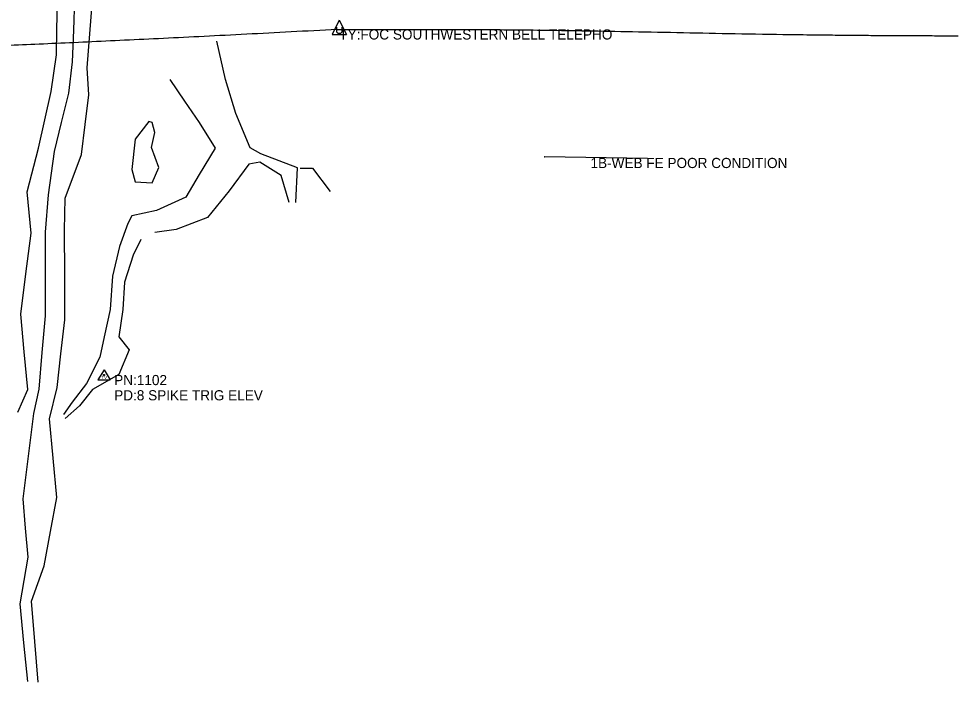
# Model space of a CAD drawing. Extents: x 976456 to 985170, y 1525951 to 1527080.
# Drawn here: x 982881.4 to 983344, y 1525950.6 to 1526277.2 of the extents above; entities that cross this region are included whole.
import ezdxf

# ---------------------------------------------------------------- set-up
doc = ezdxf.new("R2010")
doc.units = 0
for name, color, linetype in [('S_DITCHLINE', 7, 'Continuous'), ('S_FENCE', 7, 'Continuous'), ('S_FIBER_OPTIC_CABLE', 7, 'Continuous'), ('S_MSC_PT_SYM', 7, 'Continuous'), ('S_SECONDARY_CTL', 7, 'Continuous'), ('S_SECONDARY_CTL_ANNOT', 7, 'Continuous'), ('S_STREAM', 7, 'Continuous'), ('S_SURVEY_TEXT_ANNOT', 7, 'Continuous'), ('S_UNDERGROUND_CABLE', 7, 'Continuous'), ('S_UTILITY_POLE_ANNOT', 7, 'Continuous')]:
    doc.layers.add(name, color=color, linetype=linetype)

msp = doc.modelspace()

# ---------------------------------------------------------------- linework, layer by layer
at = {"layer": 'S_DITCHLINE'}
for points in [[(983017.87, 1526186.79), (983018.61, 1526203.88), (983000.6, 1526210.79), (982995.33, 1526213.63), (982988.23, 1526230.62), (982983.19, 1526247.38), (982978.84, 1526266.28)], [(982955.72, 1526247.28), (982962.94, 1526236.71), (982970.15, 1526226.13), (982978.07, 1526213.6), (982970.21, 1526200.62), (982963.63, 1526189.41), (982949.16, 1526182.77), (982937.08, 1526180.12), (982935.06, 1526176.37), (982930.93, 1526165.11), (982927.61, 1526150.46), (982926.38, 1526134.1), (982923.45, 1526120.61), (982921.28, 1526110.67), (982914.7, 1526097.64), (982907.73, 1526088.52), (982903.37, 1526082.32)], [(983014.54, 1526186.73), (983010.67, 1526200.06), (983000.04, 1526206.58), (982994.65, 1526205.64), (982985.01, 1526192.59), (982974.38, 1526179.43), (982958.93, 1526173.53), (982948.4, 1526172.01)], [(983019.88, 1526203.75), (983026.02, 1526203.6), (983034.8, 1526192.25)], [(982941.46, 1526168.58), (982937.64, 1526160.83), (982933.41, 1526147.54), (982932.67, 1526134.05), (982930.64, 1526120.7), (982935.79, 1526114.19), (982930.71, 1526102.09), (982917.74, 1526094.62), (982911.35, 1526086.71), (982904.16, 1526080.48)]]:
    msp.add_lwpolyline(points, dxfattribs=at)
msp.add_lwpolyline([(982945.37, 1526226.68), (982938.78, 1526217.88), (982937.05, 1526202.94), (982938.72, 1526196.93), (982947.05, 1526196.46), (982950.29, 1526204.02), (982946.78, 1526213.93), (982948.39, 1526221.18), (982947.09, 1526226.08)], close=True, dxfattribs=at)
at = {"layer": 'S_FENCE'}
msp.add_line((983191.06, 1526208.5), (983140.2, 1526209.24), dxfattribs=at)
at = {"layer": 'S_FIBER_OPTIC_CABLE'}
for points in [[(983038.02, 1526271.95), (982776.59, 1526257.91), (982699.02, 1526265.54), (982301.76, 1526204.82)], [(983038.02, 1526271.95), (983068.37, 1526271.95), (983136.25, 1526271.95), (983282.54, 1526268.9), (983343.98, 1526268.9)]]:
    msp.add_open_spline(points, degree=2, dxfattribs=at)
at = {"layer": 'S_MSC_PT_SYM'}
for points in [[(983140.2, 1526209.24), (983140.2, 1526209.29), (983140.2, 1526209.24), (983140.15, 1526209.24), (983140.2, 1526209.24), (983140.2, 1526209.19), (983140.2, 1526209.24), (983140.25, 1526209.24)], [(983162.92, 1526208.73), (983162.92, 1526208.78), (983162.92, 1526208.73), (983162.87, 1526208.73), (983162.92, 1526208.73), (983162.92, 1526208.68), (983162.92, 1526208.73), (983162.97, 1526208.73)], [(983191.06, 1526208.5), (983191.06, 1526208.55), (983191.06, 1526208.5), (983191.01, 1526208.5), (983191.06, 1526208.5), (983191.06, 1526208.45), (983191.06, 1526208.5), (983191.11, 1526208.5)]]:
    msp.add_lwpolyline(points, dxfattribs=at)
at = {"layer": 'S_SECONDARY_CTL'}
for p, q in [((982923.37, 1526104.45), (982920.36, 1526099.49)), ((982923.37, 1526104.45), (982926.32, 1526099.49)), ((982920.36, 1526099.49), (982926.32, 1526099.49))]:
    msp.add_line(p, q, dxfattribs=at)
for radius in [0.311, 0.183, 0.103]:
    msp.add_circle((982923.37, 1526101.84), radius, dxfattribs=at)
at = {"layer": 'S_STREAM'}
for points in [[(982885.91, 1525950.85), (982883.96, 1525969.98), (982882.01, 1525989.11), (982885.94, 1526012.05), (982884.71, 1526026.44), (982883.48, 1526040.83), (982886.16, 1526061.86), (982888.84, 1526082.9), (982891.41, 1526094.88), (982892.97, 1526112.9), (982894.54, 1526130.91), (982894.51, 1526151.51), (982894.48, 1526172.11), (982895.96, 1526190.47), (982898.93, 1526211.82), (982902.45, 1526226.24), (982905.98, 1526240.65), (982907.9, 1526256.07), (982908.43, 1526271.62), (982908.96, 1526287.18)], [(982880.87, 1526083.56), (982885.84, 1526094.66), (982884.09, 1526113.25), (982882.34, 1526131.83), (982884.94, 1526151.71), (982887.53, 1526171.6), (982885.5, 1526191.95), (982891.1, 1526213.48), (982894.18, 1526227.42), (982897.26, 1526241.36), (982899.89, 1526259.5), (982900.18, 1526272.17), (982900.46, 1526284.84)], [(982890.93, 1525950.55), (982889.33, 1525970.52), (982887.72, 1525990.49), (982893.85, 1526007.94), (982897.01, 1526024.76), (982900.16, 1526041.58), (982898.34, 1526060.94), (982896.51, 1526080.3), (982900.22, 1526095.61), (982902.18, 1526112.27), (982904.14, 1526128.93), (982904.04, 1526151.04), (982903.94, 1526173.15), (982904.18, 1526188.89), (982912.33, 1526210.41), (982914.11, 1526225.12), (982915.89, 1526239.83), (982915.07, 1526253.02), (982916.38, 1526269.85), (982917.7, 1526286.69)]]:
    msp.add_lwpolyline(points, dxfattribs=at)
at = {"layer": 'S_UNDERGROUND_CABLE'}
for p, q in [((983039.22, 1526276.55), (983035.7, 1526269.46)), ((983038.02, 1526270.7), (983038.02, 1526273.14)), ((983039.22, 1526276.55), (983042.71, 1526269.46)), ((983040.39, 1526273.14), (983040.39, 1526270.7)), ((983035.7, 1526269.46), (983042.71, 1526269.46)), ((983038.64, 1526270.04), (983038.02, 1526270.7)), ((983039.84, 1526270.04), (983038.64, 1526270.04)), ((983040.39, 1526270.7), (983039.84, 1526270.04))]:
    msp.add_line(p, q, dxfattribs=at)

# ---------------------------------------------------------------- texts
at = {"layer": 'S_SECONDARY_CTL'}
msp.add_text('TV', height=1.5, rotation=360, dxfattribs=at).set_placement((982922.17, 1526099.82))
at = {"layer": 'S_SECONDARY_CTL_ANNOT'}
for s, p in [('PN:1102', (982928.37, 1526096.84)), ('PD:8 SPIKE TRIG ELEV', (982928.37, 1526089.34))]:
    msp.add_text(s, height=5, dxfattribs=at).set_placement(p)
at = {"layer": 'S_SURVEY_TEXT_ANNOT'}
msp.add_text('1B-WEB FE POOR CONDITION', height=5, dxfattribs=at).set_placement((983162.92, 1526203.73))
at = {"layer": 'S_UTILITY_POLE_ANNOT'}
msp.add_text('TY:FOC SOUTHWESTERN BELL TELEPHO', height=5, dxfattribs=at).set_placement((983039.22, 1526267.02))

doc.saveas('drawing.dxf')
